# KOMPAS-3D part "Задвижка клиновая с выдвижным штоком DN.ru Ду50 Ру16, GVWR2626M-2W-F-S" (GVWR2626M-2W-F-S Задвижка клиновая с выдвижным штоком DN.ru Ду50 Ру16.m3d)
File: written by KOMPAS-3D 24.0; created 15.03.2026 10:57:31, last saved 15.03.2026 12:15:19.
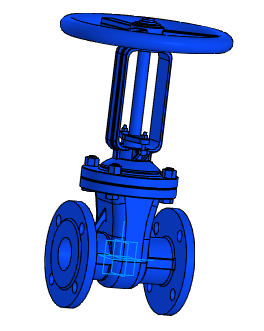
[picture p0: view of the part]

Document properties: Автор: R2D2; Полное имя файла: E:\Работа\Зайцев\GVWR2626M-2W-F-S Задвижка клиновая с выдвижным штоком DN.ru Ду50-300 Ру16\DN50\GVWR2626M-2W-F-S Задвижка клиновая с выдвижным штоком DN.ru Ду50 Ру16.m3d

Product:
- Part/product: Задвижка клиновая с выдвижным штоком DN.ru Ду50 Ру16  | designation GVWR2626M-2W-F-S
    Масса: 15.5
    Раздел спецификации: Прочие изделия
    Примечание: D040-10499

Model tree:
1. Операция без истории:2

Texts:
  GVWR2626M-2W-F-S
